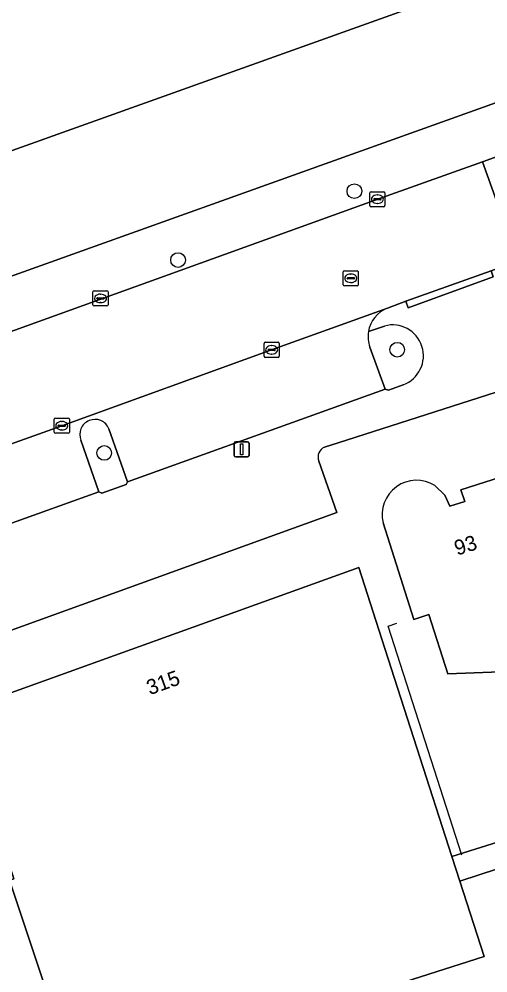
# Model space of a CAD drawing. Extents: x 159499 to 160349, y 382524 to 383273.
# Drawn here: x 159623.7 to 159654.8, y 382873.9 to 382937.3 of the extents above; entities that cross this region are included whole.
import ezdxf

# ---------------------------------------------------------------- set-up
doc = ezdxf.new("R2010")
doc.units = 0
for name, color, linetype in [('IMGEO_Boom', 7, 'Continuous'), ('IMGEO_Erf', 7, 'Continuous'), ('IMGEO_Groenvoorziening', 7, 'Continuous'), ('IMGEO_Hek', 7, 'Continuous'), ('IMGEO_Kolk', 7, 'Continuous'), ('IMGEO_Lichtmast', 7, 'Continuous'), ('IMGEO_Pand', 7, 'Continuous'), ('IMGEO_Pand_nummerreeks', 7, 'Continuous'), ('IMGEO_Parkeervlak_open', 7, 'Continuous'), ('IMGEO_Rijbaan_lokaal_open', 7, 'Continuous'), ('IMGEO_Rioolput', 7, 'Continuous'), ('IMGEO_Voetpad_open', 7, 'Continuous')]:
    doc.layers.add(name, color=color, linetype=linetype)

msp = doc.modelspace()

# ---------------------------------------------------------------- linework, layer by layer
at = {"layer": 'IMGEO_Boom'}
for centre in [(159645.974, 382925.833), (159634.254, 382921.255), (159648.818, 382915.299), (159629.343, 382908.442)]:
    msp.add_circle(centre, 0.489, dxfattribs=at)
at = {"layer": 'IMGEO_Erf'}
for points in [[(159678.739, 382919.975), (159644.884, 382909.119), (159643.985, 382908.831)], [(159677.627, 382884.962), (159674.658, 382884.016), (159673.774, 382886.788), (159652.977, 382879.994), (159654.595, 382874.974), (159627.613, 382866.357), (159623.043, 382880.046), (159623.336, 382880.144), (159623.263, 382880.365), (159621.679, 382885.107), (159616.505, 382883.25), (159614.32, 382889.33), (159646.264, 382900.819), (159647.798, 382896.061), (159652.453, 382881.618), (159666.269, 382885.977), (159665.394, 382888.751), (159669.71, 382890.113), (159670.586, 382887.339), (159686.697, 382892.422), (159684.344, 382903.803), (159682.972, 382908.111), (159679.314, 382919.635)], [(159679.569, 382913.801), (159681.564, 382907.552), (159680.565, 382907.218), (159681.828, 382903.268), (159677.654, 382900.516), (159675.017, 382898.777), (159667.039, 382898.465), (159660.329, 382894.075), (159652.192, 382893.754), (159650.919, 382897.697), (159649.918, 382897.379)], [(159651.325, 382906.275), (159651.983, 382905.642), (159652.32, 382904.9), (159653.303, 382905.215), (159653.051, 382905.989), (159656.228, 382907.004), (159659.371, 382908.008), (159659.626, 382907.243), (159660.608, 382907.568), (159660.484, 382908.373), (159660.694, 382909.101)], [(159643.613, 382907.896), (159644.801, 382904.486), (159612.925, 382892.967), (159610.264, 382891.992), (159611.791, 382887.214), (159603.56, 382884.583), (159601.436, 382891.228), (159609.667, 382893.859), (159607.935, 382899.05)], [(159649.918, 382897.379), (159647.879, 382903.798)]]:
    msp.add_lwpolyline(points, dxfattribs=at)
for centre, radius, start, end in [((159644.265, 382908.178), 0.711, 113.23039, 203.37825), ((159650.104, 382904.338), 2.29, 57.78923, 193.62826)]:
    msp.add_arc(centre, radius, start, end, dxfattribs=at)
at = {"layer": 'IMGEO_Groenvoorziening'}
for points in [[(159685.537, 382944.38), (159682.676, 382958.981), (159682.454, 382960.802), (159675.818, 382961.931), (159676.134, 382961.046), (159680.442, 382948.993), (159609.134, 382923.507), (159606.674, 382930.391), (159601.595, 382928.556), (159605.894, 382916.702)], [(159610.141, 382915.546), (159684.209, 382942.053)], [(159647.971, 382916.875), (159646.904, 382916.504)], [(159646.997, 382915.471), (159648.028, 382912.677), (159648.233, 382912.604), (159649.22, 382912.971)], [(159627.798, 382909.285), (159628.992, 382905.852), (159629.19, 382905.777), (159630.791, 382906.347), (159630.9, 382906.525), (159629.655, 382910.049)]]:
    msp.add_lwpolyline(points, dxfattribs=at)
for centre, radius, start, end in [((159648.51, 382914.896), 2.051, 290.24313, 105.23876), ((159649.054, 382916.177), 2.175, 171.34763, 198.9412), ((159628.693, 382909.674), 0.976, 111.03545, 203.47469), ((159628.74, 382909.683), 0.986, 21.82348, 113.73289)]:
    msp.add_arc(centre, radius, start, end, dxfattribs=at)
at = {"layer": 'IMGEO_Hek'}
for points in [[(159648.209, 382896.936), (159648.803, 382897.14)], [(159653.111, 382881.712), (159648.209, 382896.936)]]:
    msp.add_lwpolyline(points, dxfattribs=at)
at = {"layer": 'IMGEO_Kolk'}
for p, q in [((159647.002, 382924.874), (159647.002, 382925.726)), ((159647.077, 382925.8), (159647.929, 382925.8)), ((159647.49, 382925.58), (159647.515, 382925.58)), ((159648.003, 382925.726), (159648.003, 382924.874)), ((159647.261, 382925.294), (159647.261, 382925.306)), ((159647.699, 382925.257), (159647.301, 382925.257)), ((159647.304, 382925.343), (159647.702, 382925.343)), ((159647.513, 382925.02), (159647.488, 382925.02)), ((159647.745, 382925.306), (159647.745, 382925.294)), ((159647.929, 382924.8), (159647.077, 382924.8)), ((159628.671, 382919.209), (159629.523, 382919.209)), ((159628.596, 382918.283), (159628.596, 382919.135)), ((159628.855, 382918.703), (159628.855, 382918.715)), ((159629.293, 382918.666), (159628.895, 382918.666)), ((159628.898, 382918.752), (159629.296, 382918.752)), ((159629.084, 382918.989), (159629.109, 382918.989)), ((159629.339, 382918.715), (159629.339, 382918.703)), ((159629.597, 382919.135), (159629.597, 382918.283)), ((159629.523, 382918.209), (159628.671, 382918.209)), ((159629.107, 382918.429), (159629.082, 382918.429)), ((159639.972, 382914.865), (159639.972, 382915.717)), ((159640.047, 382915.791), (159640.899, 382915.791)), ((159640.46, 382915.571), (159640.485, 382915.571)), ((159640.973, 382915.717), (159640.973, 382914.865)), ((159640.899, 382914.791), (159640.047, 382914.791)), ((159640.231, 382915.285), (159640.231, 382915.297)), ((159640.669, 382915.248), (159640.271, 382915.248)), ((159640.274, 382915.334), (159640.672, 382915.334)), ((159640.483, 382915.011), (159640.458, 382915.011)), ((159640.715, 382915.297), (159640.715, 382915.285)), ((159626.024, 382909.825), (159626.024, 382910.677)), ((159626.099, 382910.751), (159626.951, 382910.751)), ((159626.326, 382910.294), (159626.724, 382910.294)), ((159626.512, 382910.531), (159626.537, 382910.531)), ((159627.025, 382910.677), (159627.025, 382909.825)), ((159626.951, 382909.751), (159626.099, 382909.751)), ((159626.283, 382910.245), (159626.283, 382910.257)), ((159626.721, 382910.208), (159626.323, 382910.208)), ((159626.535, 382909.971), (159626.51, 382909.971)), ((159626.767, 382910.257), (159626.767, 382910.245))]:
    msp.add_line(p, q, dxfattribs=at)
for points in [[(159647.002, 382924.874), (159647.002, 382925.726)], [(159647.077, 382925.8), (159647.929, 382925.8)], [(159648.003, 382925.726), (159648.003, 382924.874)], [(159647.929, 382924.8), (159647.077, 382924.8)], [(159628.671, 382919.209), (159629.523, 382919.209)], [(159628.596, 382918.283), (159628.596, 382919.135)], [(159629.597, 382919.135), (159629.597, 382918.283)], [(159629.523, 382918.209), (159628.671, 382918.209)], [(159639.972, 382914.865), (159639.972, 382915.717)], [(159640.047, 382915.791), (159640.899, 382915.791)], [(159640.973, 382915.717), (159640.973, 382914.865)], [(159640.899, 382914.791), (159640.047, 382914.791)], [(159626.024, 382909.825), (159626.024, 382910.677)], [(159626.099, 382910.751), (159626.951, 382910.751)], [(159627.025, 382910.677), (159627.025, 382909.825)], [(159626.951, 382909.751), (159626.099, 382909.751)]]:
    msp.add_lwpolyline(points, dxfattribs=at)
for centre, radius, start, end in [((159647.079, 382925.724), 0.0765, 91.55205, 178.44795), ((159647.079, 382925.724), 0.0765, 91.55205, 178.44795), ((159647.927, 382925.724), 0.0765, 1.55205, 88.44795), ((159647.927, 382925.724), 0.0765, 1.55205, 88.44795), ((159647.079, 382924.876), 0.0765, 181.55205, 268.44795), ((159647.079, 382924.876), 0.0765, 181.55205, 268.44795), ((159647.301, 382925.303), 0.0403, 85.87752, 175.75265), ((159647.298, 382925.293), 0.0366, 178.93798, 274.71019), ((159647.702, 382925.3), 0.043, 264.86636, 352.45326), ((159647.706, 382925.305), 0.0386, 1.73085, 96.63898), ((159647.927, 382924.876), 0.0765, 271.55205, 358.44795), ((159647.927, 382924.876), 0.0765, 271.55205, 358.44795), ((159628.673, 382919.133), 0.0765, 91.55205, 178.44795), ((159628.673, 382919.133), 0.0765, 91.55205, 178.44795), ((159629.521, 382919.133), 0.0765, 1.55205, 88.44795), ((159629.521, 382919.133), 0.0765, 1.55205, 88.44795), ((159628.895, 382918.712), 0.0403, 85.87752, 175.75265), ((159628.892, 382918.702), 0.0366, 178.93798, 274.71019), ((159629.296, 382918.709), 0.043, 264.86636, 352.45326), ((159629.3, 382918.714), 0.0386, 1.73085, 96.63898), ((159628.673, 382918.285), 0.0765, 181.55205, 268.44795), ((159628.673, 382918.285), 0.0765, 181.55205, 268.44795), ((159629.521, 382918.285), 0.0765, 271.55205, 358.44795), ((159629.521, 382918.285), 0.0765, 271.55205, 358.44795), ((159640.049, 382915.715), 0.0765, 91.55205, 178.44795), ((159640.049, 382915.715), 0.0765, 91.55205, 178.44795), ((159640.897, 382915.715), 0.0765, 1.55205, 88.44795), ((159640.897, 382915.715), 0.0765, 1.55205, 88.44795), ((159640.049, 382914.867), 0.0765, 181.55205, 268.44795), ((159640.049, 382914.867), 0.0765, 181.55205, 268.44795), ((159640.271, 382915.294), 0.0403, 85.87752, 175.75265), ((159640.268, 382915.284), 0.0366, 178.93798, 274.71019), ((159640.672, 382915.291), 0.043, 264.86636, 352.45326), ((159640.676, 382915.296), 0.0386, 1.73085, 96.63898), ((159640.897, 382914.867), 0.0765, 271.55205, 358.44795), ((159640.897, 382914.867), 0.0765, 271.55205, 358.44795), ((159626.101, 382910.675), 0.0765, 91.55205, 178.44795), ((159626.101, 382910.675), 0.0765, 91.55205, 178.44795), ((159626.323, 382910.254), 0.0403, 85.87752, 175.75265), ((159626.728, 382910.256), 0.0386, 1.73085, 96.63898), ((159626.949, 382910.675), 0.0765, 1.55205, 88.44795), ((159626.949, 382910.675), 0.0765, 1.55205, 88.44795), ((159626.101, 382909.827), 0.0765, 181.55205, 268.44795), ((159626.101, 382909.827), 0.0765, 181.55205, 268.44795), ((159626.32, 382910.244), 0.0366, 178.93798, 274.71019), ((159626.724, 382910.251), 0.043, 264.86636, 352.45326), ((159626.949, 382909.827), 0.0765, 271.55205, 358.44795), ((159626.949, 382909.827), 0.0765, 271.55205, 358.44795)]:
    msp.add_arc(centre, radius, start, end, dxfattribs=at)
for centre, major_axis, ratio, start_param, end_param in [((159647.489, 382925.3), (-0.387, 0.002), 0.722429, 4.712389, 7.853982), ((159647.514, 382925.3), (-0.39, 0.002), 0.717154, 1.570796, 4.712389), ((159629.083, 382918.709), (-0.387, 0.002), 0.722429, 4.712389, 7.853982), ((159629.108, 382918.709), (-0.39, 0.002), 0.717154, 1.570796, 4.712389), ((159640.459, 382915.291), (-0.387, 0.002), 0.722429, 4.712389, 7.853982), ((159640.484, 382915.291), (-0.39, 0.002), 0.717154, 1.570796, 4.712389), ((159626.511, 382910.251), (-0.387, 0.002), 0.722429, 4.712389, 7.853982), ((159626.536, 382910.251), (-0.39, 0.002), 0.717154, 1.570796, 4.712389)]:
    msp.add_ellipse(centre, major_axis=major_axis, ratio=ratio, start_param=start_param, end_param=end_param, dxfattribs=at)
at = {"layer": 'IMGEO_Lichtmast'}
for p, q in [((159637.982, 382908.279), (159637.982, 382909.079)), ((159637.982, 382909.079), (159637.982, 382908.279)), ((159638.082, 382909.179), (159638.872, 382909.179)), ((159638.872, 382909.179), (159638.082, 382909.179)), ((159638.972, 382909.079), (159638.972, 382908.279)), ((159638.972, 382908.279), (159638.972, 382909.079)), ((159638.872, 382908.179), (159638.082, 382908.179)), ((159638.082, 382908.179), (159638.872, 382908.179))]:
    msp.add_line(p, q, dxfattribs=at)
msp.add_lwpolyline([(159638.402, 382909.054), (159638.552, 382909.054), (159638.552, 382908.304), (159638.402, 382908.304), (159638.402, 382909.054)], dxfattribs=at)
for centre, start, end in [((159638.082, 382909.079), 90, 180), ((159638.082, 382909.079), 90, 180), ((159638.872, 382909.079), 0, 90), ((159638.872, 382909.079), 360, 90), ((159638.082, 382908.279), 180, 270), ((159638.082, 382908.279), 180, 270), ((159638.872, 382908.279), 270, 0), ((159638.872, 382908.279), 270, 0)]:
    msp.add_arc(centre, 0.1, start, end, dxfattribs=at)
at = {"layer": 'IMGEO_Pand'}
for points in [[(159622.779, 382941.693), (159621.91, 382944.124), (159621.758, 382944.07), (159613.077, 382940.968), (159614.525, 382937.123), (159605.702, 382933.97), (159605.077, 382935.718), (159604.805, 382935.62), (159604.862, 382935.46), (159606.674, 382930.391), (159609.134, 382923.507), (159680.442, 382948.993), (159676.134, 382961.046), (159676.022, 382961.006), (159675.913, 382960.967), (159676.004, 382960.713), (159676.516, 382959.279), (159624.918, 382940.838), (159623.292, 382940.257)], [(159647.798, 382896.061), (159646.264, 382900.819), (159614.32, 382889.33), (159616.505, 382883.25), (159621.679, 382885.107), (159623.263, 382880.365), (159623.336, 382880.144), (159623.043, 382880.046), (159627.613, 382866.357), (159654.595, 382874.974), (159652.977, 382879.994), (159652.453, 382881.618)]]:
    msp.add_lwpolyline(points, close=True, dxfattribs=at)
msp.add_lwpolyline([(159647.879, 382903.798), (159649.918, 382897.379), (159650.919, 382897.697), (159652.192, 382893.754), (159660.329, 382894.075), (159656.228, 382907.004), (159653.051, 382905.989), (159653.303, 382905.215), (159652.32, 382904.9), (159651.983, 382905.642), (159651.325, 382906.275)], dxfattribs=at)
msp.add_arc((159650.104, 382904.338), 2.29, 57.78923, 193.62826, dxfattribs=at)
at = {"layer": 'IMGEO_Parkeervlak_open'}
for points in [[(159648.172, 382918.059), (159640.473, 382915.292), (159626.524, 382910.252), (159613.1, 382905.468), (159610.87, 382904.686)], [(159629.655, 382910.049), (159630.9, 382906.525), (159648.028, 382912.677), (159646.997, 382915.471)], [(159613.354, 382903.304), (159614.27, 382900.585), (159628.992, 382905.852), (159627.798, 382909.285)]]:
    msp.add_lwpolyline(points, dxfattribs=at)
for centre, radius, start, end in [((159648.892, 382916.177), 2.015, 110.94053, 170.66952), ((159649.054, 382916.177), 2.175, 171.34763, 198.9412), ((159628.693, 382909.674), 0.976, 111.03545, 203.47469), ((159628.74, 382909.683), 0.986, 21.82348, 113.73289)]:
    msp.add_arc(centre, radius, start, end, dxfattribs=at)
at = {"layer": 'IMGEO_Rijbaan_lokaal_open'}
msp.add_lwpolyline([(159661.264, 382922.76), (159658.894, 382929.37), (159654.498, 382927.794), (159656.866, 382921.189)], close=True, dxfattribs=at)
for points in [[(159640.473, 382915.292), (159648.172, 382918.059), (159649.397, 382918.517), (159655.068, 382920.54), (159655.602, 382920.738), (159656.866, 382921.189), (159654.498, 382927.794), (159648.081, 382925.494), (159612.644, 382912.722), (159610.022, 382911.818)], [(159607.16, 382903.726), (159610.716, 382904.646), (159610.87, 382904.686), (159613.1, 382905.468), (159626.524, 382910.252), (159640.473, 382915.292)]]:
    msp.add_lwpolyline(points, dxfattribs=at)
at = {"layer": 'IMGEO_Rioolput'}
for p, q in [((159645.233, 382919.62), (159645.233, 382920.472)), ((159645.308, 382920.546), (159646.16, 382920.546)), ((159646.234, 382920.472), (159646.234, 382919.62)), ((159645.492, 382920.04), (159645.492, 382920.052)), ((159645.93, 382920.003), (159645.532, 382920.003)), ((159645.535, 382920.089), (159645.933, 382920.089)), ((159645.721, 382920.326), (159645.746, 382920.326)), ((159645.976, 382920.052), (159645.976, 382920.04)), ((159646.16, 382919.546), (159645.308, 382919.546)), ((159645.744, 382919.766), (159645.719, 382919.766))]:
    msp.add_line(p, q, dxfattribs=at)
for points in [[(159645.233, 382919.62), (159645.233, 382920.472)], [(159645.308, 382920.546), (159646.16, 382920.546)], [(159646.234, 382920.472), (159646.234, 382919.62)], [(159646.16, 382919.546), (159645.308, 382919.546)]]:
    msp.add_lwpolyline(points, dxfattribs=at)
for centre, radius, start, end in [((159645.31, 382920.47), 0.0765, 91.55205, 178.44795), ((159645.31, 382920.47), 0.0765, 91.55205, 178.44795), ((159646.158, 382920.47), 0.0765, 1.55205, 88.44795), ((159646.158, 382920.47), 0.0765, 1.55205, 88.44795), ((159645.532, 382920.049), 0.0403, 85.87752, 175.75265), ((159645.529, 382920.039), 0.0366, 178.93798, 274.71019), ((159645.933, 382920.046), 0.043, 264.86636, 352.45326), ((159645.937, 382920.051), 0.0386, 1.73085, 96.63898), ((159645.31, 382919.622), 0.0765, 181.55205, 268.44795), ((159645.31, 382919.622), 0.0765, 181.55205, 268.44795), ((159646.158, 382919.622), 0.0765, 271.55205, 358.44795), ((159646.158, 382919.622), 0.0765, 271.55205, 358.44795)]:
    msp.add_arc(centre, radius, start, end, dxfattribs=at)
for centre, major_axis, ratio, start_param, end_param in [((159645.72, 382920.046), (-0.387, 0.002), 0.722429, 4.712389, 7.853982), ((159645.745, 382920.046), (-0.39, 0.002), 0.717154, 1.570796, 4.712389)]:
    msp.add_ellipse(centre, major_axis=major_axis, ratio=ratio, start_param=start_param, end_param=end_param, dxfattribs=at)
at = {"layer": 'IMGEO_Voetpad_open'}
for points in [[(159684.209, 382942.053), (159610.141, 382915.546)], [(159610.022, 382911.818), (159612.644, 382912.722), (159648.081, 382925.494), (159654.498, 382927.794), (159658.894, 382929.37), (159684.231, 382938.452)], [(159670.727, 382926.129), (159669.682, 382925.77), (159669.821, 382925.346), (159664.14, 382923.322), (159663.986, 382923.732), (159661.264, 382922.76), (159656.866, 382921.189), (159655.602, 382920.738), (159655.068, 382920.54), (159655.202, 382920.132), (159649.547, 382918.093), (159649.397, 382918.517), (159648.172, 382918.059)], [(159643.985, 382908.831), (159644.884, 382909.119), (159678.739, 382919.975), (159680.586, 382920.586)], [(159679.314, 382919.635), (159682.972, 382908.111), (159684.344, 382903.803), (159686.697, 382892.422), (159670.586, 382887.339), (159666.269, 382885.977), (159652.453, 382881.618), (159652.977, 382879.994), (159673.774, 382886.788), (159678.411, 382888.266), (159686.978, 382891.063), (159696.341, 382875.806), (159697.782, 382876.31), (159691.913, 382886.147), (159689.55, 382889.865), (159688.195, 382891.998), (159687.876, 382894.008), (159685.785, 382904.242), (159680.586, 382920.586)], [(159646.904, 382916.504), (159647.971, 382916.875)], [(159649.22, 382912.971), (159648.233, 382912.604), (159648.028, 382912.677), (159630.9, 382906.525), (159630.791, 382906.347), (159629.19, 382905.777), (159628.992, 382905.852), (159614.27, 382900.585), (159613.354, 382903.304)], [(159610.87, 382904.686), (159610.716, 382904.646), (159612.319, 382899.727), (159610.909, 382899.221), (159610.951, 382899.13), (159610.752, 382899.054), (159612.925, 382892.967), (159644.801, 382904.486), (159643.613, 382907.896)]]:
    msp.add_lwpolyline(points, dxfattribs=at)
msp.add_lwpolyline([(159655.068, 382920.54), (159649.397, 382918.517), (159649.547, 382918.093), (159655.202, 382920.132)], close=True, dxfattribs=at)
for centre, radius, start, end in [((159648.892, 382916.177), 2.015, 110.94053, 170.66952), ((159648.51, 382914.896), 2.051, 290.24313, 105.23876), ((159644.265, 382908.178), 0.711, 113.23039, 203.37825)]:
    msp.add_arc(centre, radius, start, end, dxfattribs=at)

# ---------------------------------------------------------------- texts
at = {"layer": 'IMGEO_Pand_nummerreeks'}
for s, rotation, p in [('93', 17.75983, (159652.801, 382901.609)), ('315', 19.78423, (159632.372, 382892.337))]:
    msp.add_text(s, height=1, rotation=rotation, dxfattribs=at).set_placement(p)

doc.saveas('drawing.dxf')
